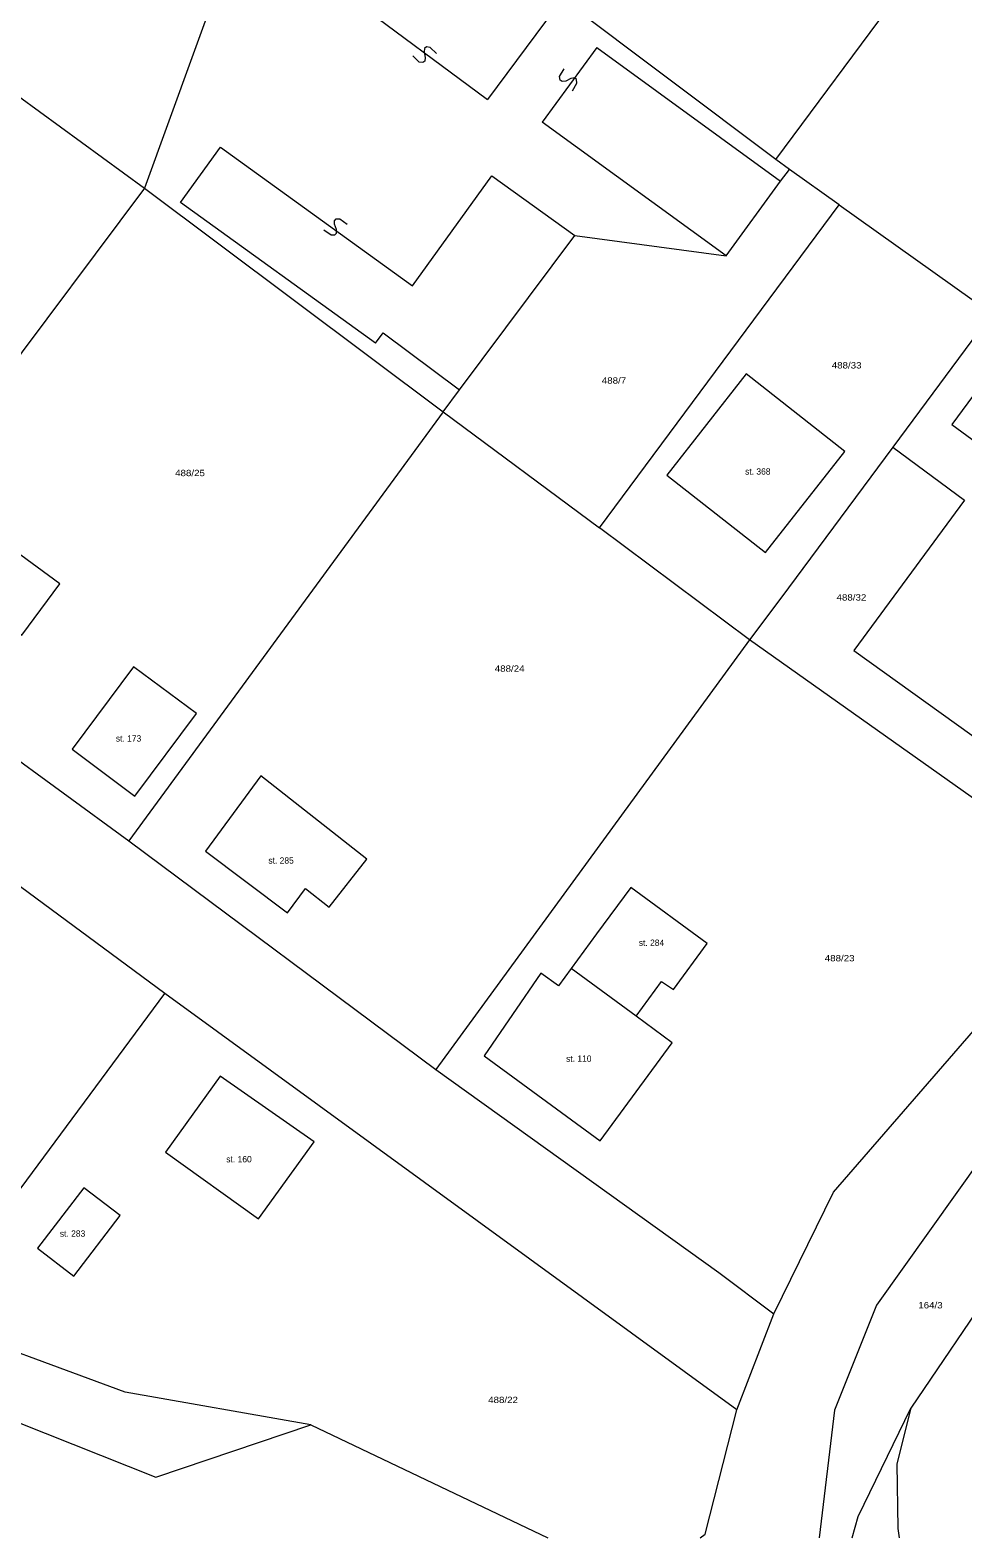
# Model space of a CAD drawing. Extents: x -694702 to -694000, y -1089746 to -1089192.
# Drawn here: x -694622.5 to -694548.9, y -1089606.5 to -1089487.5 of the extents above; entities that cross this region are included whole.
import ezdxf

# ---------------------------------------------------------------- set-up
doc = ezdxf.new("R2010")
doc.units = 0
doc.header["$LTSCALE"] = 0.2
doc.layers.add('50', color=7, linetype='Continuous', lineweight=13)
doc.layers.add('52', color=7, linetype='Continuous', lineweight=13)

msp = doc.modelspace()

# ---------------------------------------------------------------- linework, layer by layer
at = {"layer": '50'}
for p, q in [((-694563.62, -1089497.74), (-694539.5, -1089465.2)), ((-694637.28, -1089482.61), (-694613.45, -1089500)), ((-694601.1, -1089482.07), (-694586.36, -1089493)), ((-694563.62, -1089497.74), (-694580.39, -1089485.1)), ((-694581.02, -1089485.81), (-694586.36, -1089493)), ((-694577.75, -1089488.89), (-694582.05, -1089494.79)), ((-694577.75, -1089488.89), (-694563.24, -1089499.45)), ((-694567.54, -1089505.35), (-694582.05, -1089494.79)), ((-694610.61, -1089501.13), (-694607.44, -1089496.75)), ((-694607.44, -1089496.75), (-694592.28, -1089507.7)), ((-694592.28, -1089507.7), (-694586.02, -1089499.02)), ((-694586.02, -1089499.02), (-694579.49, -1089503.73)), ((-694613.45, -1089500), (-694625.84, -1089516.56)), ((-694613.45, -1089500), (-694589.86, -1089517.64)), ((-694595.21, -1089512.24), (-694610.61, -1089501.13)), ((-694577.54, -1089526.81), (-694558.62, -1089501.3)), ((-694595.21, -1089512.24), (-694594.6, -1089511.42)), ((-694594.6, -1089511.42), (-694588.59, -1089515.91)), ((-694589.86, -1089517.64), (-694614.68, -1089551.51)), ((-694589.86, -1089517.64), (-694577.54, -1089526.81)), ((-694565.68, -1089535.66), (-694577.54, -1089526.81)), ((-694638.82, -1089533.91), (-694614.68, -1089551.51)), ((-694565.68, -1089535.66), (-694590.45, -1089569.57)), ((-694611.84, -1089563.58), (-694632.26, -1089548.47)), ((-694614.68, -1089551.51), (-694590.45, -1089569.57)), ((-694574.65, -1089565.36), (-694579.77, -1089561.6)), ((-694630.82, -1089589.19), (-694611.84, -1089563.58)), ((-694566.7, -1089596.43), (-694611.84, -1089563.58)), ((-694543.01, -1089581.61), (-694552.96, -1089596.31)), ((-694566.7, -1089596.43), (-694563.76, -1089588.86)), ((-694600.32, -1089597.63), (-694581.62, -1089606.54))]:
    msp.add_line(p, q, dxfattribs=at)
for points in [[(-694622.21, -1089465.48), (-694609.86, -1089475.7), (-694607.68, -1089484.09), (-694613.45, -1089500)], [(-694558.62, -1089501.3), (-694562.53, -1089498.51), (-694563.62, -1089497.74)], [(-694589.86, -1089517.64), (-694588.59, -1089515.91), (-694579.49, -1089503.73), (-694567.54, -1089505.35), (-694563.24, -1089499.45), (-694562.53, -1089498.51)], [(-694558.62, -1089501.3), (-694546.56, -1089509.88), (-694554.38, -1089520.43)], [(-694554.38, -1089520.43), (-694563.23, -1089532.36), (-694565.68, -1089535.66)], [(-694554.38, -1089520.43), (-694548.72, -1089524.63), (-694557.45, -1089536.48), (-694535.56, -1089552.2)], [(-694538.16, -1089555.18), (-694540.61, -1089553.41), (-694565.68, -1089535.66)], [(-694574.65, -1089565.36), (-694572.64, -1089562.62), (-694571.69, -1089563.26), (-694569.02, -1089559.63), (-694575.07, -1089555.19), (-694577.76, -1089558.86), (-694579.77, -1089561.6)], [(-694563.76, -1089588.86), (-694559.06, -1089579.24), (-694538.16, -1089555.18)], [(-694579.77, -1089561.6), (-694580.78, -1089562.97), (-694582.15, -1089561.97), (-694586.63, -1089568.48), (-694577.47, -1089575.2), (-694571.79, -1089567.46), (-694574.65, -1089565.36)], [(-694590.45, -1089569.57), (-694568.1, -1089585.59), (-694563.76, -1089588.86)], [(-694545.41, -1089573.81), (-694547.31, -1089576.44), (-694555.66, -1089588.18), (-694558.98, -1089596.45), (-694560.19, -1089606.54)], [(-694671.82, -1089578.19), (-694612.56, -1089601.76), (-694600.32, -1089597.63)], [(-694600.32, -1089597.63), (-694614.98, -1089595.05), (-694630.82, -1089589.19)], [(-694569.59, -1089606.54), (-694569.2, -1089606.25), (-694566.7, -1089596.43)], [(-694557.58, -1089606.54), (-694557.1, -1089604.86), (-694552.96, -1089596.31)], [(-694552.96, -1089596.31), (-694554.06, -1089600.71), (-694553.99, -1089605.79), (-694553.88, -1089606.54)]]:
    msp.add_lwpolyline(points, dxfattribs=at)
for points in [[(-694564.42, -1089528.76), (-694558.16, -1089520.77), (-694565.95, -1089514.66), (-694572.21, -1089522.65)], [(-694542.8, -1089519.38), (-694547.64, -1089515.83), (-694549.71, -1089518.65), (-694544.87, -1089522.2)], [(-694627.71, -1089538.19), (-694624.73, -1089534.11), (-694623.12, -1089535.29), (-694620.13, -1089531.22), (-694629, -1089524.74), (-694634.96, -1089532.89)], [(-694609.35, -1089541.47), (-694614.32, -1089537.77), (-694619.17, -1089544.29), (-694614.2, -1089547.99)], [(-694595.89, -1089552.96), (-694604.27, -1089546.39), (-694608.64, -1089552.34), (-694602.17, -1089557.2), (-694600.73, -1089555.29), (-694598.88, -1089556.75)], [(-694600.06, -1089575.28), (-694607.47, -1089570.1), (-694611.79, -1089576.09), (-694604.44, -1089581.37)], [(-694618.23, -1089578.9), (-694621.9, -1089583.68), (-694619.03, -1089585.88), (-694615.36, -1089581.1)]]:
    msp.add_lwpolyline(points, close=True, dxfattribs=at)
at = {"layer": '52'}
for points in [[(-694590.396, -1089489.372), (-694590.898, -1089488.884), (-694591.18, -1089488.842), (-694591.343, -1089488.962), (-694591.371, -1089489.245), (-694591.287, -1089489.683), (-694591.322, -1089489.959), (-694591.477, -1089490.086), (-694591.767, -1089490.051), (-694592.262, -1089489.556)], [(-694579.661, -1089492.315), (-694579.322, -1089491.703), (-694579.356, -1089491.418), (-694579.514, -1089491.293), (-694579.795, -1089491.34), (-694580.195, -1089491.537), (-694580.471, -1089491.576), (-694580.635, -1089491.459), (-694580.677, -1089491.17), (-694580.329, -1089490.562)], [(-694599.282, -1089503.276), (-694598.716, -1089503.688), (-694598.43, -1089503.69), (-694598.286, -1089503.548), (-694598.298, -1089503.264), (-694598.444, -1089502.842), (-694598.448, -1089502.564), (-694598.312, -1089502.416), (-694598.02, -1089502.41), (-694597.46, -1089502.83)]]:
    msp.add_lwpolyline(points, dxfattribs=at)

# ---------------------------------------------------------------- texts
at = {"layer": '52', "width": 1.15}
for s, p in [('488/33', (-694559.2, -1089514.23)), ('488/7', (-694577.35, -1089515.43)), ('488/25', (-694611.03, -1089522.73)), ('488/32', (-694558.82, -1089532.55)), ('488/24', (-694585.8, -1089538.17)), ('488/23', (-694559.75, -1089561.03)), ('164/3', (-694552.37, -1089588.43)), ('488/22', (-694586.32, -1089595.9))]:
    msp.add_text(s, height=0.5, dxfattribs=at).set_placement(p)
at = {"layer": '52'}
for s, p in [('st. 368', (-694566.04, -1089522.61)), ('st. 173', (-694615.71, -1089543.68)), ('st. 285', (-694603.67, -1089553.32)), ('st. 284', (-694574.43, -1089559.81)), ('st. 110', (-694580.17, -1089568.96)), ('st. 160', (-694606.99, -1089576.9)), ('st. 283', (-694620.13, -1089582.77))]:
    msp.add_text(s, height=0.5, dxfattribs=at).set_placement(p)

doc.saveas('drawing.dxf')
